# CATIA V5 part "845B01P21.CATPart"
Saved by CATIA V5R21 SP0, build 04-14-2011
Part number: 845B01P21
Bounding box of the stored display mesh (mm): x -76.5 to 76.5, y -25.54 to 25.54, z -6.5 to 6.5
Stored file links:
  C:\Users\ALI OZGUN\Desktop\alhan\845B01P21.CATPart
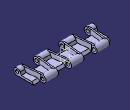
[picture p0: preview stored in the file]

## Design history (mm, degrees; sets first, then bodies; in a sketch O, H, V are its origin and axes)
Body1 (main body)
  Sketch1 on yz-plane, origin (0, 0, 0), H (0, 1, 0), V (0, 0, 1)
    construction line L1 (-19.05, 0) -> (19.05, 0)
    point P1 (-19.05, 0)
    point P2 (19.05, 0)
    line L2 (-19.05, 6.5) -> (19.05, 6.5)
    line L3 (19.05, -6.5) -> (-19.05, -6.5)
    arc A1 centre (19.05, 0) radius 6.5 from (19.05, 6.5) to (19.05, -6.5) cw
    arc A2 centre (-19.05, 0) radius 6.5 from (-19.05, -6.5) to (-19.05, 6.5) cw
    circle A3 centre (19.05, 0) radius 3.25
    circle A4 centre (-19.05, 0) radius 3.25
    distance L1 L2 = 6.5
    length L1 = 38.1
    distance P2 V = 19.05
    radius A3 = 3.25
    radius A4 = 3.25
    coincidence: P1 H
    horizontal: L1 H
    tangency: A1 L2, A2 L2, A1 L3, A2 L3
  Pad1: profile Sketch1, direction (1, 0, 0), length 76.5, mirrored extent
  Sketch2 on face of Pad1 from Sketch1.L2, origin (0, 0, 6.5), H (1, 0, 0), V (0, 1, 0)
    line L1 (38, -14) -> (64, -14)
    line L2 (64, -14) -> (64, -36.0786)
    line L3 (64, -36.0786) -> (38, -36.0786)
    line L4 (38, -36.0786) -> (38, -14)
    line L5 (-13, -14) -> (13, -14)
    line L6 (13, -14) -> (13, -36.0786)
    line L7 (13, -36.0786) -> (-13, -36.0786)
    line L8 (-13, -36.0786) -> (-13, -14)
    point P7 (13, -36.0786)
    line L9 (-64, -14) -> (-38, -14)
    line L10 (-38, -14) -> (-38, -32.269)
    line L11 (-38, -32.269) -> (-64, -32.269)
    line L12 (-64, -32.269) -> (-64, -14)
    line L13 (85.7823, 31.3847) -> (63.5, 31.3847)
    line L14 (63.5, 31.3847) -> (63.5, 14)
    line L15 (63.5, 14) -> (85.7823, 14)
    line L16 (85.7823, 14) -> (85.7823, 31.3847)
    point P17 (12.5, 31.3847)
    line L17 (12.5, 31.3847) -> (38.5, 31.3847)
    line L18 (38.5, 31.3847) -> (38.5, 14)
    line L19 (38.5, 14) -> (12.5, 14)
    line L20 (12.5, 14) -> (12.5, 31.3847)
    point P19 (38.5, 14)
    line L21 (-38.5, 32.0801) -> (-12.5, 32.0801)
    line L22 (-12.5, 32.0801) -> (-12.5, 14)
    line L23 (-12.5, 14) -> (-38.5, 14)
    line L24 (-38.5, 14) -> (-38.5, 32.0801)
    point P23 (-12.5, 14)
    line L25 (-81.4786, 33.8185) -> (-63.5, 33.8185)
    line L26 (-63.5, 33.8185) -> (-63.5, 14)
    line L27 (-63.5, 14) -> (-81.4786, 14)
    line L28 (-81.4786, 14) -> (-81.4786, 33.8185)
    point P27 (-63.5, 14)
    reference projected line E1 (76.5, 19.05) -> (76.5, -19.05) from edge [face of Pad1 from Sketch1.L2 | end face of Pad1]
    reference projected line E2 (-76.5, 19.05) -> (-76.5, -19.05) from edge [start face of Pad1 | face of Pad1 from Sketch1.L2]
    reference projected line E3 (-76.5, 19.05) -> (-76.5, -19.05) from edge [start face of Pad1 | face of Pad1 from Sketch1.L2]
    reference projected line E4 (76.5, 19.05) -> (76.5, -19.05) from edge [face of Pad1 from Sketch1.L2 | end face of Pad1]
    distance L14 E1 = 13
    distance L26 E2 = 13
    distance L12 E3 = 12.5
    distance L2 E4 = 12.5
    distance L23 L5 = 28
    distance L5 H = 14
    distance L4 L2 = 26
    distance L12 L10 = 26
    distance L10 L8 = 25
    distance L6 L4 = 25
    distance L24 L26 = 25
    distance L18 L14 = 25
    distance L26 L22 = 51
    distance L20 L18 = 26
    horizontal: L1 H, L3 H, L5 H, L7 H, L9 H, L11 H, L13 H, L15 H, L17 H, L19 H, L21 H, L23 H, L25 H, L27 H
    vertical: L2 V, L4 V, L6 V, L8 V, L10 V, L12 V, L14 V, L16 V, L18 V, L20 V, L22 V, L24 V, L26 V, L28 V
    coincidence: P7 L3, P17 L13, P19 L15, P23 L15, P27 L15, L1 L5, L9 L5
  Pocket1: profile Sketch2, direction (0, 0, -1), length 53.5
  Sketch3 on end face of Pad1, origin (76.5, 0, 0), H (0, 1, 0), V (0, 0, 1)
    projected arc E1 centre (19.05, 0) radius 6.5 from (19.05, -6.5) to (19.05, 6.5) ccw from edge [face of Pocket1 from Sketch2.L14 | face of Pad1 from Sketch1.A1]
    projected arc E2 centre (19.05, 0) radius 6.5 from (19.05, -6.5) to (13.0358, 2.4657) ccw from edge [face of Pocket1 from Sketch2.L14 | face of Pad1 from Sketch1.A1]
    point P1 (19.05, -6.5)
    projected arc E3 centre (-19.05, 0) radius 6.5 from (-19.05, 6.5) to (-19.05, -6.5) ccw from edge [face of Pad1 from Sketch1.A2 | end face of Pad1]
    projected arc E4 centre (-19.05, 0) radius 6.5 from (-13.0358, 2.4657) to (-19.05, -6.5) ccw from edge [face of Pad1 from Sketch1.A2 | end face of Pad1]
    point P4 (-19.05, -6.5)
    projected line E5 (-19.05, -6.5) -> (14, -6.5) from edge [face of Pad1 from Sketch1.L3 | end face of Pad1]
    point P5 (-19.05, -6.5)
    projected line E6 (19.05, -6.5) -> (14, -6.5) from edge [face of Pocket1 from Sketch2.L14 | face of Pad1 from Sketch1.L3]
    point P7 (19.05, -6.5)
    line L1 (-13.0358, 2.4657) -> (-11, -2.5)
    line L2 (-11, -2.5) -> (11, -2.5)
    point P10 (11, -2.5)
    line L3 (11, -2.5) -> (13.0358, 2.4657)
    distance L2 E5 = 4
    length L2 = 22
    distance P10 V = 11
    horizontal: L2 H
    tangency: L3 E1, L1 E3
    coincidence: P1 P7, P4 P5
  Pocket2: profile Sketch3, direction (-1, 0, 0), length 172.5, outer side
  Sketch4 on face of Pocket2 from Sketch3.L2, origin (0, 0, -2.5), H (1, 0, 0), V (0, 1, 0)
    projected line E1 (38, -14) -> (38, -25.55) from edge [face of Pocket2 | face of Pocket1 from Sketch2.L4]
    projected line E2 (38, -14) -> (38, -19.05) from edge [face of Pocket2 | face of Pocket1 from Sketch2.L4]
    point P1 (38, -14)
    point P2 (38, -25.55)
    projected line E3 (13, -25.55) -> (13, -14) from edge [face of Pocket2 | face of Pocket1 from Sketch2.L6]
    projected line E4 (13, -19.05) -> (13, -14) from edge [face of Pocket2 | face of Pocket1 from Sketch2.L6]
    point P3 (13, -25.55)
    point P4 (13, -14)
    projected line E5 (64, -25.55) -> (64, -14) from edge [face of Pocket2 | face of Pocket1 from Sketch2.L2]
    projected line E6 (64, -19.05) -> (64, -14) from edge [face of Pocket2 | face of Pocket1 from Sketch2.L2]
    point P5 (64, -25.55)
    point P6 (64, -14)
    projected line E7 (38.5, 14) -> (38.5, 25.55) from edge [face of Pocket2 | face of Pocket1 from Sketch2.L18]
    projected line E8 (38.5, 14) -> (38.5, 19.05) from edge [face of Pocket2 | face of Pocket1 from Sketch2.L18]
    point P7 (38.5, 14)
    point P8 (38.5, 25.55)
    projected line E9 (63.5, 14) -> (63.5, 25.55) from edge [face of Pocket1 from Sketch2.L14 | face of Pocket2]
    projected line E10 (63.5, 14) -> (63.5, 19.05) from edge [face of Pocket1 from Sketch2.L14 | face of Pocket2]
    point P9 (63.5, 14)
    point P10 (63.5, 25.55)
    projected line E11 (12.5, 25.55) -> (12.5, 14) from edge [face of Pocket2 | face of Pocket1 from Sketch2.L20]
    projected line E12 (12.5, 19.05) -> (12.5, 14) from edge [face of Pocket2 | face of Pocket1 from Sketch2.L20]
    point P11 (12.5, 25.55)
    point P12 (12.5, 14)
    offset line E13 (9.5, 25.55) -> (9.5, 14) from edge [face of Pocket2 | face of Pocket1 from Sketch2.L20]
    offset line E14 (9.5, 19.05) -> (9.5, 14) from edge [face of Pocket2 | face of Pocket1 from Sketch2.L20]
    point P13 (9.5, 25.55)
    point P14 (9.5, 14)
    offset line E15 (16, -25.55) -> (16, -14) from edge [face of Pocket2 | face of Pocket1 from Sketch2.L6]
    offset line E16 (16, -19.05) -> (16, -14) from edge [face of Pocket2 | face of Pocket1 from Sketch2.L6]
    point P15 (16, -25.55)
    point P16 (16, -14)
    offset line E17 (35, -14) -> (35, -25.55) from edge [face of Pocket2 | face of Pocket1 from Sketch2.L4]
    offset line E18 (35, -14) -> (35, -19.05) from edge [face of Pocket2 | face of Pocket1 from Sketch2.L4]
    point P17 (35, -14)
    point P18 (35, -25.55)
    offset line E19 (41.5, 14) -> (41.5, 25.55) from edge [face of Pocket2 | face of Pocket1 from Sketch2.L18]
    offset line E20 (41.5, 14) -> (41.5, 19.05) from edge [face of Pocket2 | face of Pocket1 from Sketch2.L18]
    point P19 (41.5, 14)
    point P20 (41.5, 25.55)
    offset line E21 (60.5, 14) -> (60.5, 25.55) from edge [face of Pocket1 from Sketch2.L14 | face of Pocket2]
    offset line E22 (60.5, 14) -> (60.5, 19.05) from edge [face of Pocket1 from Sketch2.L14 | face of Pocket2]
    point P21 (60.5, 14)
    point P22 (60.5, 25.55)
    offset line E23 (67, -25.55) -> (67, -14) from edge [face of Pocket2 | face of Pocket1 from Sketch2.L2]
    offset line E24 (67, -19.05) -> (67, -14) from edge [face of Pocket2 | face of Pocket1 from Sketch2.L2]
    point P23 (67, -25.55)
    point P24 (67, -14)
    line L1 (13, -14) -> (9.5, 14)
    line L2 (16, -14) -> (12.5, 14)
    line L3 (35, -14) -> (38.5, 14)
    line L4 (38, -14) -> (41.5, 14)
    line L5 (64, -14) -> (60.5, 14)
    line L6 (67, -14) -> (63.5, 14)
    projected line E25 through (0, -19.05) direction (1, 0) from axis of face of Pocket2
    projected line E26 (13, -19.05) -> (16, -19.05) from axis of face of Pocket2
    projected line E27 (64, -19.05) -> (67, -19.05) from axis of face of Pocket2
    projected line E28 (35, -19.05) -> (38, -19.05) from axis of face of Pocket2
    point P25 (-10000000, -19.05)
    point P26 (10000000, -19.05)
    point P27 (67, -19.05)
    point P28 (38, -19.05)
    point P29 (64, -19.05)
    point P30 (64, -19.05)
    point P31 (38, -19.05)
    point P32 (35, -19.05)
    point P33 (16, -19.05)
    point P34 (35, -19.05)
    point P35 (16, -19.05)
    point P36 (13, -19.05)
    point P37 (13, -19.05)
    projected line E29 through (0, 19.05) direction (1, 0) from axis of face of Pocket2
    projected line E30 (9.5, 19.05) -> (12.5, 19.05) from axis of face of Pocket2
    projected line E31 (38.5, 19.05) -> (41.5, 19.05) from axis of face of Pocket2
    projected line E32 (60.5, 19.05) -> (63.5, 19.05) from axis of face of Pocket2
    point P38 (-10000000, 19.05)
    point P39 (10000000, 19.05)
    point P40 (63.5, 19.05)
    point P41 (9.5, 19.05)
    point P42 (9.5, 19.05)
    point P43 (12.5, 19.05)
    point P44 (12.5, 19.05)
    point P45 (38.5, 19.05)
    point P46 (38.5, 19.05)
    point P47 (41.5, 19.05)
    point P48 (60.5, 19.05)
    point P49 (41.5, 19.05)
    point P50 (60.5, 19.05)
    point P51 (-10000000, -19.05)
    point P52 (10000000, -19.05)
    point P53 (-10000000, 19.05)
    point P54 (10000000, 19.05)
    construction line L7 through (0, -19.05) direction (-1, 0)
    construction line L8 through (0, 19.05) direction (-1, 0)
    point P55 (-10000000, -19.05)
    point P56 (10000000, -19.05)
    point P57 (-16, -19.05)
    point P58 (-13, -19.05)
    point P59 (-67, -19.05)
    point P60 (-64, -19.05)
    point P61 (-38, -19.05)
    point P62 (-35, -19.05)
    point P63 (-38, -25.55)
    point P64 (-38, -14)
    point P65 (-38, -19.05)
    point P66 (-13, -14)
    point P67 (-13, -25.55)
    point P68 (-13, -19.05)
    point P69 (-64, -14)
    point P70 (-64, -25.55)
    point P71 (-64, -19.05)
    point P72 (-38.5, 25.55)
    point P73 (-38.5, 14)
    point P74 (-38.5, 19.05)
    point P75 (-63.5, 25.55)
    point P76 (-63.5, 14)
    point P77 (-63.5, 19.05)
    point P78 (-12.5, 14)
    point P79 (-12.5, 25.55)
    point P80 (-12.5, 19.05)
    point P81 (-9.5, 14)
    point P82 (-9.5, 25.55)
    point P83 (-9.5, 19.05)
    point P84 (-16, -14)
    point P85 (-16, -25.55)
    point P86 (-16, -19.05)
    point P87 (-35, -25.55)
    point P88 (-35, -14)
    point P89 (-35, -19.05)
    point P90 (-41.5, 25.55)
    point P91 (-41.5, 14)
    point P92 (-41.5, 19.05)
    point P93 (-60.5, 25.55)
    point P94 (-60.5, 14)
    point P95 (-60.5, 19.05)
    point P96 (-67, -14)
    point P97 (-67, -25.55)
    line L9 (-13, -14) -> (-9.5, 14)
    line L10 (-16, -14) -> (-12.5, 14)
    line L11 (-35, -14) -> (-38.5, 14)
    line L12 (-38, -14) -> (-41.5, 14)
    line L13 (-64, -14) -> (-60.5, 14)
    line L14 (-67, -14) -> (-63.5, 14)
    point P98 (-10000000, 19.05)
    point P99 (10000000, 19.05)
    point P100 (-12.5, 19.05)
    point P101 (-9.5, 19.05)
    point P102 (-41.5, 19.05)
    point P103 (-38.5, 19.05)
    point P104 (-60.5, 19.05)
    construction line L15 through (0, -19.05) direction (-1, 0)
    line L16 (-13, -19.05) -> (-16, -19.05)
    line L17 (-64, -19.05) -> (-67, -19.05)
    line L18 (-35, -19.05) -> (-38, -19.05)
    construction line L19 (-38, -14) -> (-38, -25.55)
    line L20 (-38, -14) -> (-38, -19.05)
    construction line L21 (-13, -25.55) -> (-13, -14)
    line L22 (-13, -19.05) -> (-13, -14)
    construction line L23 (-64, -25.55) -> (-64, -14)
    line L24 (-64, -19.05) -> (-64, -14)
    construction line L25 (-38.5, 14) -> (-38.5, 25.55)
    line L26 (-38.5, 14) -> (-38.5, 19.05)
    construction line L27 (-63.5, 14) -> (-63.5, 25.55)
    line L28 (-63.5, 14) -> (-63.5, 19.05)
    construction line L29 (-12.5, 25.55) -> (-12.5, 14)
    line L30 (-12.5, 19.05) -> (-12.5, 14)
    construction line L31 (-9.5, 25.55) -> (-9.5, 14)
    line L32 (-9.5, 19.05) -> (-9.5, 14)
    construction line L33 (-16, -25.55) -> (-16, -14)
    line L34 (-16, -19.05) -> (-16, -14)
    construction line L35 (-35, -14) -> (-35, -25.55)
    line L36 (-35, -14) -> (-35, -19.05)
    construction line L37 (-41.5, 14) -> (-41.5, 25.55)
    line L38 (-41.5, 14) -> (-41.5, 19.05)
    construction line L39 (-60.5, 14) -> (-60.5, 25.55)
    line L40 (-60.5, 14) -> (-60.5, 19.05)
    construction line L41 (-67, -25.55) -> (-67, -14)
    line L42 (-67, -19.05) -> (-67, -14)
    construction line L43 through (0, 19.05) direction (-1, 0)
    line L44 (-9.5, 19.05) -> (-12.5, 19.05)
    line L45 (-38.5, 19.05) -> (-41.5, 19.05)
    line L46 (-60.5, 19.05) -> (-63.5, 19.05)
    parallelism: L2 L1, L4 L3
    coincidence: E1 P28, E5 P29, E25 P30, E25 P31, E25 P32, E15 P33, E17 P34, E25 P35, E25 P36, E3 P37, E13 P41, E29 P42, E29 P43, E11 P44, E7 P45, E29 P46, E29 P47, E29 P48, E19 P49, E21 P50, P28 P31, P29 P30, P32 P34, P33 P35, P36 P37, P41 P42, P43 P44, P45 P46, P47 P49, P48 P50
    symmetry: P26 P51 V, P25 P52 V, E25 L7 V, P39 P53 V, P38 P54 V, E29 L8 V, P26 P55 V, P25 P56 V, P33 P57 V, P37 P58 V, P27 P59 V, P29 P60 V, P28 P61 V, P34 P62 V, E25 L15 V, P2 P63 V, P1 P64 V, P31 P65 V, E1 L19 V, P4 P66 V, P3 P67 V, P36 P68 V, E3 L21 V, P6 P69 V, P5 P70 V, P30 P71 V, E5 L23 V, P8 P72 V, P7 P73 V, P46 P74 V, E7 L25 V, P10 P75 V, P9 P76 V, P40 P77 V, E9 L27 V, P12 P78 V, P11 P79 V, P43 P80 V, E11 L29 V, P14 P81 V, P13 P82 V, P42 P83 V, E13 L31 V, P16 P84 V, P15 P85 V, P35 P86 V, E15 L33 V, P18 P87 V, P17 P88 V, P32 P89 V, E17 L35 V, P20 P90 V, P19 P91 V, P47 P92 V, E19 L37 V, P22 P93 V, P21 P94 V, P48 P95 V, E21 L39 V, P24 P96 V, P23 P97 V, E23 L41 V, L1 L9 V, L2 L10 V, L3 L11 V, L4 L12 V, L5 L13 V, L6 L14 V, P39 P98 V, P38 P99 V, P44 P100 V, P41 P101 V, P49 P102 V, P45 P103 V, P50 P104 V, E29 L43 V, E25 L18 V, E25 L17 V, E25 L16 V, E1 L20 V, E3 L22 V, E5 L24 V, E7 L26 V, E9 L28 V, E11 L30 V, E13 L32 V, E15 L34 V, E17 L36 V, E19 L38 V, E21 L40 V, E23 L42 V, E29 L46 V, E29 L45 V, E29 L44 V
  Pad2: profile Sketch4, direction (0, 0, 1), length 9
  Sketch5 on yz-plane, origin (0, 0, 0), H (0, 1, 0), V (0, 0, 1)
    projected circle E1 centre (-19.05, 0) radius 3.25 from edge [end face of Pad1 | face of Pad1 from Sketch1.A4]
    circle A1 centre (19.05, 0) radius 3.25
    reference projected circle E2 centre (19.05, 0) radius 3.25 from edge [face of Pad1 from Sketch1.A3 | face of Pad2]
    coincidence: A1 E2
  Pocket3: profile Sketch5, direction (-1, 0, 0), length 95, mirrored extent
  RemoveFace1: RemoveFaces (face of Pocket2 from Sketch3.L3; face of Pocket2; face of Pocket2 from Sketch3.L3; face of Pocket2; face of Pocket2 from Sketch3.L1; face of Pocket2; face of Pocket2 from Sketch3.L1; face of Pocket2; face of Pocket2; face of Pocket2; face of Pocket2; face of Pocket2 from Sketch3.L3; face of Pocket2 from Sketch3.L3; face of Pocket2 from Sketch3.L1)
  Chamfer1: length 4, angle 45, on edge [face of Pocket1 from Sketch2.L27 | face of Pocket2 from Sketch3.L2]; edge [face of Pocket1 from Sketch2.L9 | face of Pocket2 from Sketch3.L2]; edge [face of Pocket1 from Sketch2.L19 | face of Pocket2 from Sketch3.L2]; edge [face of Pocket1 from Sketch2.L5 | face of Pocket2 from Sketch3.L2]; edge [face of Pocket1 from Sketch2.L1 | face of Pocket2 from Sketch3.L2]; edge [face of Pocket1 from Sketch2.L15 | face of Pocket2 from Sketch3.L2]; edge [face of Pocket1 from Sketch2.L23 | face of Pocket2 from Sketch3.L2]
Body2
  Solid1: linked copy from another document
  Translate1: Direction zx-plane, ToTransfor Solid1, Length 38.1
